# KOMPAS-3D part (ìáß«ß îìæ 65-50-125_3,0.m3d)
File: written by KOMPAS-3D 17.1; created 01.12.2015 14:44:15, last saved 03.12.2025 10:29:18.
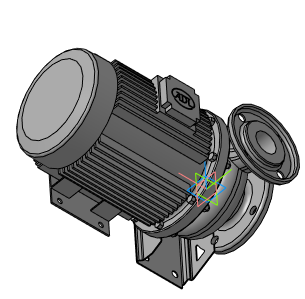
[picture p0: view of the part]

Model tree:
1. Операция без истории:2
